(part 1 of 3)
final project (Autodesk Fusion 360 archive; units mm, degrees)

design "final project" references "Enclosure"
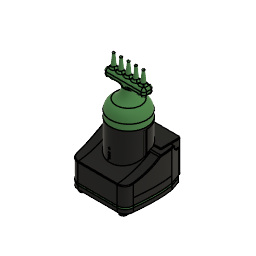
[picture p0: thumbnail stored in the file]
description: Part Number
part number: Micro USB PD Board
part number: Top Toggle Switch
description: STEP AP214
part number: USB Type C Port (SMD Type)
part number: Screw-Terminal-P5.08
part number: ESSOP-10 Package v5
part number: Pin1Body
part number: Pin2Body
part number: CeramicBody
part number: CoatingBody
description: FreeCAD Model
part number: Resistor_0603
part number: Pin1
part number: Pin2
part number: CeramicBody_1
part number: Ceramic_Capacitor_0402_h20mil
part number: 0603 Chip SMD LED (1.6x0.8mm)
sketch "Sketch1" plane through (0, 0, 0) normal (0, 0, 1) x axis (1, 0, 0)
  line L1 (-41, -45) -> (41, -45)
  line L2 (-41, 23.9998) -> (-41, -45)
  line L3 (27.5, 45) -> (-27.5, 45)
  line L4 (41, -45) -> (41, 23.9998)
  line L5 (-41, 45) -> (41, -45)
  line L6 (41, 45) -> (-41, -45)
  line L7 (27.5, 45) -> (0, 45)
  line L8 (-27.5, 45) -> (0, 45)
  line L9 (-27.5, 40) -> (-27.5, 45)
  line L10 (27.5, 40) -> (27.5, 45)
  line L11 (-35.5, 40) -> (-27.5, 40)
  line L12 (-41, 23.9998) -> (-35.5, 40)
  line L13 (35.5, 40) -> (27.5, 40)
  line L14 (41, 23.9998) -> (35.5, 40)
  point P6 (0, 0)
  point P1 (0, 0)
  point P7 (0, 45)
  point P4 (-41, 45)
  point P5 (41, 45)
  point P3 (-41, -45)
  point P8 (27.5, 45)
  point P9 (-27.5, 45)
  point P10 (-27.5, 40)
  point P12 (-35.5, 40)
  point P11 (27.5, 40)
  point P15 (35.5, 40)
  horizontal L1
  perpendicular L1 L2
  parallel L1 L3
  parallel L2 L4
  coincident L5 P6
  coincident L6 P6
  coincident P1 P6
  parallel L3 L7
  parallel L3 L8
  perpendicular L8 L9
  perpendicular L3 L10
  perpendicular L9 L11
  perpendicular L10 L13
  coincident L3 P7
  dimension "d1" distance P4 P5 = 82
  dimension "d2" distance P3 P4 = 90
  dimension "d3" distance P7 P8 = 27.5
  dimension "d4" distance P7 P9 = 27.5
  dimension "d5" distance P10 P12 = 8
  dimension "d6" distance P11 P15 = 8
extrude "Extrude1" new body sketch "Sketch1" profile of L1 L2 L3 L4 L7 L8 L9 L10 L11 L12 L13 L14 along normal blind 7.5
fillet "Fillet2" radius 12
sketch "Sketch2" plane through (0, 0, 7.5) normal (0, 0, 1) x axis (-1, 0, 0)
  line L1 (-41, -23.9998) -> (-41, 33)
  line L2 (-35.5, -40) -> (-41, -23.9998)
  line L3 (-27.5, -40) -> (-35.5, -40)
  line L4 (-27.5, -45) -> (-27.5, -40)
  line L5 (27.5, -45) -> (-27.5, -45)
  line L6 (27.5, -40) -> (27.5, -45)
  line L7 (35.5, -40) -> (27.5, -40)
  line L8 (41, -23.9998) -> (35.5, -40)
  line L9 (41, 33) -> (41, -23.9998)
  line L10 (-29, 45) -> (29, 45)
  curve K1 (41, -23.9998) -> (41, 33)
  line L11 (41, 33.316) -> (41, -23.9998)
  arc A1 centre (-29, 33) radius 12 clockwise from (-41, 33) to (-29, 45)
  arc A2 centre (29, 33) radius 12 clockwise from (29, 45) to (41, 33)
  point P21 (41, 33)
  point P24 (41, 33)
  point P19 (41, -23.9998)
  point P26 (41, -23.9998)
  coincident P21 P24
  coincident P19 P26
  parallel L9 L11
extrude "Extrude2" add sketch "Sketch2" profile of L9 K1 against normal blind 7.5
sketch "Sketch3" plane through (0, 0, 7.5) normal (0, 0, 1) x axis (-1, 0, 0)
  line L1 (-41, -23.9998) -> (-41, 33)
  line L2 (-35.5, -40) -> (-41, -23.9998)
  line L3 (-27.5, -40) -> (-35.5, -40)
  line L4 (-27.5, -45) -> (-27.5, -40)
  line L5 (27.5, -45) -> (-27.5, -45)
  line L6 (27.5, -40) -> (27.5, -45)
  line L7 (35.5, -40) -> (27.5, -40)
  line L8 (41, -23.9998) -> (35.5, -40)
  curve K1 (41, -23.9998) -> (41, 33)
  line L9 (-29, 45) -> (29, 45)
  curve K2 (-41, -23.9998) -> (-41, 33)
  line L10 (-41, 33) -> (-41, -23.9998)
  arc A1 centre (-29, 33) radius 12 clockwise from (-41, 33) to (-29, 45)
  arc A2 centre (29, 33) radius 12 clockwise from (29, 45) to (41, 33)
  tangent A1 L10
extrude "Extrude3" add sketch "Sketch3" profile of L1 K2 against normal blind 7.5
sketch "Sketch4" plane through (0, 0, 7.5) normal (0, 0, 1) x axis (-1, 0, 0)
  curve K1 (-41, -23.9998) -> (-41, 33)
  line L1 (-35.5, -40) -> (-41, -23.9998)
  line L2 (-27.5, -40) -> (-35.5, -40)
  line L3 (-27.5, -45) -> (-27.5, -40)
  line L4 (27.5, -45) -> (-27.5, -45)
  line L5 (27.5, -40) -> (27.5, -45)
  line L6 (35.5, -40) -> (27.5, -40)
  line L7 (41, -23.9998) -> (35.5, -40)
  curve K2 (41, -23.9998) -> (41, 33)
  line L8 (-29, 45) -> (29, 45)
  line L9 (31.5, -51.6365) -> (35.5, -40)
  line L10 (37, -45) -> (27.5, -45)
  line L11 (-27.5, -45) -> (37, -45)
  line L12 (-36, -45) -> (-27.5, -45)
  line L13 (-31, -51) -> (-35.5, -40)
  arc A1 centre (-29, 33) radius 12 clockwise from (-41, 33) to (-29, 45)
  arc A2 centre (29, 33) radius 12 clockwise from (29, 45) to (41, 33)
  point P11 (35.5, -40)
  point P16 (35.5, -40)
  point P9 (27.5, -45)
  point P18 (27.5, -45)
  point P8 (-27.5, -45)
  point P20 (-27.5, -45)
  point P21 (-27.5, -45)
  point P6 (-35.5, -40)
  point P23 (-35.5, -40)
  coincident P11 P16
  parallel L7 L9
  coincident P9 P18
  perpendicular L5 L10
  coincident P8 P20
  coincident P8 P21
  perpendicular L3 L12
  coincident P6 P23
fillet "Fillet3" radius 2
extrude "Extrude4" new body sketch "Sketch4" along normal blind 35
fillet "Fillet5" radius 4
sketch "Sketch5" plane through (0, 0, 0) normal (1, 0, 0) x axis (0, 1, 0)
  line L1 (-40, 25) -> (-40, 0)
  line L2 (5, 25) -> (-40, 25)
  line L3 (5, 42.7761) -> (5, 25)
  line L4 (-46.8828, 42.7761) -> (5, 42.7761)
  line L5 (-48.9914, 25) -> (-46.8828, 42.7761)
  line L6 (-40, 25) -> (-48.9914, 25)
  point P2 (-40, 0)
  point P3 (-40, 25)
  vertical L1
  perpendicular L1 L2
  perpendicular L2 L3
  perpendicular L3 L4
  perpendicular L1 L6
  dimension "d26" distance P2 P3 = 25
extrude "Extrude5" cut sketch "Sketch5" profile of L2 L3 L4 L5 L6 distance 65
chamfer "Chamfer1" distance 17.5
sketch "Sketch6" plane through (0, 0, 42.5) normal (0, 0, 1) x axis (-1, 0, 0)
  line L1 (-42.7553, -5) -> (42.7553, -5)
  curve K1 (-41, -23.9998) -> (-42.7553, -5)
  line L2 (-35.5, -40) -> (-41, -23.9998)
  line L3 (-34.4713, -42.5145) -> (-35.5, -40)
  line L4 (30.9265, -45) -> (-30.7691, -45)
  line L5 (41, -23.9998) -> (34.7093, -42.3003)
  curve K2 (42.7553, -5) -> (41, -23.9998)
  arc A1 centre (-30.7691, -41) radius 4 clockwise from (-30.7691, -45) to (-34.4713, -42.5145)
  arc A2 centre (30.9265, -41) radius 4 clockwise from (34.7093, -42.3003) to (30.9265, -45)
fillet "Fillet6" radius 5
fillet "Fillet7" radius 115
sketch "Sketch7" plane through (0, 0, 7.5) normal (0, 0, -1) x axis (1, 0, 0)
  line L1 (30.7691, -45) -> (-30.9265, -45)
  line L2 (35.5, -40) -> (34.4713, -42.5145)
  line L3 (41, -23.9998) -> (35.5, -40)
  curve K1 (41, -23.9998) -> (41, 33)
  line L4 (-29, 45) -> (29, 45)
  curve K2 (-41, -23.9998) -> (-41, 33)
  line L5 (-34.7093, -42.3003) -> (-41, -23.9998)
  line L6 (-15, -30) -> (15, -30)
  line L7 (-15, -20) -> (15, -30)
  line L8 (15, -20) -> (-15, -30)
  line L9 (0, -15) -> (0, -25)
  line L10 (-20, -15) -> (-15, -30)
  line L11 (20, -15) -> (15, -30)
  arc A1 centre (-30.9265, -41) radius 4 clockwise from (-30.9265, -45) to (-34.7093, -42.3003)
  arc A2 centre (30.7691, -41) radius 4 clockwise from (34.4713, -42.5145) to (30.7691, -45)
  arc A3 centre (29, 33) radius 12 clockwise from (29, 45) to (41, 33)
  arc A4 centre (-29, 33) radius 12 clockwise from (-41, 33) to (-29, 45)
  circle C1 centre (0, 0) radius 25
  point P1 (0, 0)
  point P17 (0, 0)
  point P22 (0, -25)
  point P23 (0, -25)
  point P25 (-20, -15)
  point P26 (20, -15)
  point P20 (-15, -20)
  point P21 (15, -20)
  point P19 (-15, -30)
  coincident P1 P17
  horizontal L6
  coincident L7 P22
  coincident L8 P22
  coincident C1 P22
  coincident P22 P23
  vertical L9
  coincident C1 P25
  perpendicular L8 L10
  coincident C1 P26
  perpendicular L7 L11
  dimension "d34" diameter C1 = 50
  dimension "d35" distance P20 P21 = 30
  dimension "d36" distance P19 P20 = 10
sketch "Sketch9" plane through (0, 0, 0) normal (0, 0, -1) x axis (1, 0, 0)
  line L1 (25.5, -45) -> (-25.5, -45)
  line L2 (27.5, -42) -> (27.5, -43)
  line L3 (34.0726, -40) -> (29.5, -40)
  line L4 (41, -23.9998) -> (35.964, -38.6502)
  curve K1 (41, 33) -> (41, -23.9998)
  line L5 (-29, 45) -> (29, 45)
  curve K2 (-41, -23.9998) -> (-41, 33)
  line L6 (-35.964, -38.6502) -> (-41, -23.9998)
  line L7 (-29.5, -40) -> (-34.0726, -40)
  line L8 (-27.5, -43) -> (-27.5, -42)
  line L9 (-26.4645, -26.4645) -> (-30, -30)
  line L10 (26.4645, -26.4645) -> (30, -30)
  arc A1 centre (-25.5, -43) radius 2 clockwise from (-25.5, -45) to (-27.5, -43)
  arc A2 centre (25.5, -43) radius 2 clockwise from (27.5, -43) to (25.5, -45)
  arc A3 centre (29.5, -42) radius 2 clockwise from (27.5, -42) to (29.5, -40)
  arc A4 centre (34.0726, -38) radius 2 clockwise from (35.964, -38.6502) to (34.0726, -40)
  arc A5 centre (29, 33) radius 12 clockwise from (29, 45) to (41, 33)
  arc A6 centre (-29, 33) radius 12 clockwise from (-41, 33) to (-29, 45)
  arc A7 centre (-34.0726, -38) radius 2 clockwise from (-34.0726, -40) to (-35.964, -38.6502)
  arc A8 centre (-29.5, -42) radius 2 clockwise from (-29.5, -40) to (-27.5, -42)
  circle C1 centre (30, -30) radius 5
  circle C2 centre (30, -30) radius 4
  circle C3 centre (-30, -30) radius 5
  circle C4 centre (-30, -30) radius 4
  circle C5 centre (30, 36.9675) radius 5
  circle C6 centre (30, 36.9675) radius 4
  circle C7 centre (-30, 36.9675) radius 5
  circle C8 centre (-30, 36.9675) radius 4
  point P30 (0, 0)
  point P1 (0, 0)
  point P29 (30, -30)
  point P31 (30, -30)
  point P28 (-30, -30)
  point P33 (-30, -30)
  point P35 (-26.4645, -26.4645)
  point P36 (26.4645, -26.4645)
  coincident L9 P30
  coincident P1 P30
  coincident P29 P31
  concentric C1 C2
  coincident P28 P33
  concentric C3 C4
  coincident C3 P35
  coincident C1 P36
  concentric C5 C6
  concentric C7 C8
  dimension "d47" diameter C1 = 10
  dimension "d48" diameter C2 = 8
  dimension "d49" diameter C3 = 10
  dimension "d50" diameter C4 = 8
  dimension "d51" diameter C5 = 10
  dimension "d52" diameter C6 = 8
  dimension "d53" diameter C7 = 10
  dimension "d54" diameter C8 = 8
extrude "Extrude8" add sketch "Sketch9" profile of C1 C2 C3 C4 C5 C6 C7 C8 along normal blind 2
chamfer "Chamfer3" distance 2
sketch "Sketch13" plane through (0, 0, 42.5) normal (0, 0, 1) x axis (-1, 0, 0)
  line L1 (-42.6731, -7.0711) -> (42.6731, -7.0711)
  line L2 (19, -36.2164) -> (-19, -36.2164)
  line L3 (19, -23.2164) -> (19, -36.2164)
  line L4 (-19, -36.2164) -> (-19, -23.2164)
  curve K1 (-41, -23.9998) -> (-42.6731, -7.0711)
  line L5 (-35.5, -40) -> (-41, -23.9998)
  line L6 (-34.4713, -42.5145) -> (-35.5, -40)
  line L7 (30.9265, -45) -> (-30.7691, -45)
  line L8 (41, -23.9998) -> (34.7093, -42.3003)
  curve K2 (42.6731, -7.0711) -> (41, -23.9998)
  arc A1 centre (0, 0) radius 30 clockwise from (19, -23.2164) to (-19, -23.2164)
  arc A2 centre (-30.7691, -41) radius 4 clockwise from (-30.7691, -45) to (-34.4713, -42.5145)
  arc A3 centre (30.9265, -41) radius 4 clockwise from (34.7093, -42.3003) to (30.9265, -45)
  point P1 (0, 0)
  point P4 (0, 0)
  point P7 (19, -23.2164)
  coincident P1 P4
  horizontal L2
  perpendicular L2 L3
  parallel L3 L4
  dimension "d77" distance L2 P7 = 13
chamfer "Chamfer6" distance 0.5
sketch "Sketch14" plane through (0, 0, 42.5) normal (0, 0, 1) x axis (-1, 0, 0)
  line L1 (-42.6731, -7.0711) -> (42.6731, -7.0711)
  line L2 (-45, -19.0561) -> (34.7114, -19.0561)
  line L3 (-60, -29.7451) -> (56.5385, -29.7451)
  line L4 (55.1805, -42.4902) -> (34.7114, -42.2654)
  line L5 (55.1805, -29.7451) -> (55.1805, -42.4902)
  line L6 (38.8772, -43.1883) -> (39.0249, -29.7451)
  line L7 (34.7114, -45.6177) -> (34.7954, -29.7451)
  curve K1 (-41, -23.9998) -> (-42.6731, -7.0711)
  line L8 (-35.5, -40) -> (-41, -23.9998)
  line L9 (-34.4713, -42.5145) -> (-35.5, -40)
  line L10 (30.9265, -45) -> (-30.7691, -45)
  line L11 (41, -23.9998) -> (34.7093, -42.3003)
  curve K2 (42.6731, -7.0711) -> (41, -23.9998)
  line L12 (0.0787, -53.7604) -> (0, 0)
  line L13 (-38.7506, -43.3019) -> (-38.9376, -29.8592)
  line L14 (-55.0559, -42.6516) -> (-34.5875, -42.3668)
  line L15 (-34.5777, -45.7191) -> (-34.7081, -29.8468)
  line L16 (60.0868, -29.5693) -> (-56.4512, -29.9105)
  arc A1 centre (-30.7691, -41) radius 4 clockwise from (-30.7691, -45) to (-34.4713, -42.5145)
  arc A2 centre (30.9265, -41) radius 4 clockwise from (34.7093, -42.3003) to (30.9265, -45)
  point P11 (55.1805, -29.7451)
  point P12 (39.0249, -29.7451)
  point P14 (34.7954, -29.7451)
  point P1 (0, 0)
  point P25 (0, 0)
  point P5 (34.7114, -42.2654)
  point P29 (-34.5875, -42.3668)
  point P8 (56.5385, -29.7451)
  point P33 (-56.4512, -29.9105)
  point P9 (-60, -29.7451)
  point P34 (60.0868, -29.5693)
  point P10 (55.1805, -42.4902)
  point P30 (-55.0559, -42.6516)
  point P27 (-38.9376, -29.8592)
  point P13 (38.8772, -43.1883)
  point P28 (-38.7506, -43.3019)
  point P31 (-34.7081, -29.8468)
  point P15 (34.7114, -45.6177)
  point P32 (-34.5777, -45.7191)
  coincident L3 P11
  perpendicular L3 L5
  coincident L3 P12
  perpendicular L4 L6
  coincident L3 P14
  coincident P1 P25
  symmetric P5 L12 P29
  symmetric P8 L12 P33
  symmetric P9 L12 P34
  symmetric P10 L12 P30
  symmetric P12 L12 P27
  symmetric P13 L12 P28
  symmetric P14 L12 P31
  symmetric P15 L12 P32
extrude "Extrude10" cut sketch "Sketch14" profile of L3 L4 L6 L7 L8 L9 L11 L13 L14 L15 L16 against normal blind 10
chamfer "Chamfer7" distance 5
sketch "Sketch15" plane through (0, 0, 42.5) normal (0, 0, 1) x axis (-1, 0, 0)
  line L1 (34.7954, -29.7451) -> (34.7292, -42.2422)
  line L2 (39.0249, -29.7451) -> (34.7954, -29.7451)
  line L3 (39.0249, -29.7457) -> (39.0249, -29.7451)
  line L4 (41, -23.9998) -> (39.0249, -29.7457)
  curve K1 (42.6731, -7.0711) -> (41, -23.9998)
  line L5 (-42.6731, -7.0711) -> (42.6731, -7.0711)
  curve K2 (-41, -23.9998) -> (-42.6731, -7.0711)
  line L6 (-38.9356, -30.0054) -> (-41, -23.9998)
  line L7 (-38.9376, -29.8592) -> (-38.9356, -30.0054)
  line L8 (-34.7081, -29.8468) -> (-38.9376, -29.8592)
  line L9 (-34.6067, -42.1835) -> (-34.7081, -29.8468)
  line L10 (-34.4713, -42.5145) -> (-34.6067, -42.1835)
  line L11 (30.9265, -45) -> (-30.7691, -45)
  line L12 (34.7292, -42.2422) -> (34.7093, -42.3003)
  line L13 (34.8734, -14.9854) -> (34.7954, -29.7451)
  line L14 (-34.8303, -14.9854) -> (-34.7081, -29.8468)
  line L15 (34.8734, -14.9854) -> (-34.8303, -14.9854)
  arc A1 centre (-30.7691, -41) radius 4 clockwise from (-30.7691, -45) to (-34.4713, -42.5145)
  arc A2 centre (30.9265, -41) radius 4 clockwise from (34.7093, -42.3003) to (30.9265, -45)
  point P3 (34.7954, -29.7451)
  point P21 (34.7954, -29.7451)
  point P13 (-34.7081, -29.8468)
  point P23 (-34.7081, -29.8468)
  coincident P3 P21
  coincident P13 P23
  horizontal L15
extrude "Extrude11" add sketch "Sketch15" profile of L1 L9 L10 A1 L11 A2 L12 L13 L14 L15 along normal blind 1
fillet "Fillet16" radius 1
chamfer "Chamfer11" distance 1
fillet "Fillet23" radius 4
fillet "Fillet24" radius 4
chamfer "Chamfer12" distance 1
move "Move1"
sketch "Sketch17" plane through (0, 0, 7.5) normal (0, 0, 1) x axis (-1, 0, 0)
  line L1 (-87.5, -42) -> (-87.5, -43)
  line L2 (-80.9274, -40) -> (-85.5, -40)
  line L3 (-74, -23.9998) -> (-79.036, -38.6502)
  curve K1 (-74, -23.9998) -> (-74, 33)
  line L4 (-144, 45) -> (-86, 45)
  curve K2 (-156, -23.9998) -> (-156, 33)
  line L5 (-150.964, -38.6502) -> (-156, -23.9998)
  line L6 (-144.5, -40) -> (-149.0726, -40)
  line L7 (-142.5, -43) -> (-142.5, -42)
  line L8 (-89.5, -45) -> (-140.5, -45)
  arc A1 centre (-89.5, -43) radius 2 clockwise from (-87.5, -43) to (-89.5, -45)
  arc A2 centre (-85.5, -42) radius 2 clockwise from (-87.5, -42) to (-85.5, -40)
  arc A3 centre (-80.9274, -38) radius 2 clockwise from (-79.036, -38.6502) to (-80.9274, -40)
  arc A4 centre (-86, 33) radius 12 clockwise from (-86, 45) to (-74, 33)
  arc A5 centre (-144, 33) radius 12 clockwise from (-156, 33) to (-144, 45)
  arc A6 centre (-149.0726, -38) radius 2 clockwise from (-149.0726, -40) to (-150.964, -38.6502)
  arc A7 centre (-144.5, -42) radius 2 clockwise from (-144.5, -40) to (-142.5, -42)
  arc A8 centre (-140.5, -43) radius 2 clockwise from (-140.5, -45) to (-142.5, -43)
extrude "Extrude1" new body sketch "Sketch17" along normal blind 3
move "Move1"
shell "Shell1" innerThickness 3
sketch "Sketch18" plane through (0, 0, 3) normal (0, 0, 1) x axis (-1, 0, 0)
  line L1 (-90.737, -41.7574) -> (-139.263, -41.7574)
  line L2 (-81.8142, -36.7574) -> (-85.5, -36.7574)
  line L3 (-77.1602, -23.2182) -> (-81.8142, -36.7574)
  curve K1 (-77.1602, -23.2182) -> (-77.244, 32.8474)
  line L4 (-144, 41.7574) -> (-86, 41.7574)
  curve K2 (-152.756, 32.8474) -> (-152.8398, -23.2182)
  line L5 (-148.1858, -36.7574) -> (-152.8398, -23.2182)
  line L6 (-144.5, -36.7574) -> (-148.1858, -36.7574)
  arc A1 centre (-85.5, -42) radius 5.2426 clockwise from (-90.737, -41.7574) to (-85.5, -36.7574)
  arc A2 centre (-86, 33) radius 8.7574 clockwise from (-86, 41.7574) to (-77.244, 32.8474)
  arc A3 centre (-144, 33) radius 8.7574 clockwise from (-152.756, 32.8474) to (-144, 41.7574)
  arc A4 centre (-144.5, -42) radius 5.2426 clockwise from (-144.5, -36.7574) to (-139.263, -41.7574)
  circle C1 centre (-90, -30) radius 5
  circle C2 centre (-140, -30) radius 5
  circle C3 centre (-140, 30) radius 5
  circle C4 centre (-90, 30) radius 5
  dimension "d116" diameter C1 = 10
  dimension "d117" diameter C2 = 10
  dimension "d118" diameter C3 = 10
  dimension "d119" diameter C4 = 10
sketch "Sketch19" plane through (0, 0, 7.507) normal (0, 0, 1) x axis (-1, 0, 0)
  circle C1 centre (-90, -30) radius 5
  circle C2 centre (-90, -30) radius 2.5
  circle C3 centre (-140, -30) radius 2.5
  circle C4 centre (-140, 30) radius 2.5
  circle C5 centre (-90, 30) radius 2.5
  concentric C1 C2
  dimension "d122" diameter C2 = 5
  dimension "d123" diameter C3 = 5
  dimension "d124" diameter C4 = 5
  dimension "d125" diameter C5 = 5
align "Align1"
align "Align2"
move "Move2"
move "Move3"
move "Move4"
sketch "Sketch20" plane through (0, 0, 10.7) normal (0, 0, 1) x axis (-1, 0, 0)
  line L1 (-142.5, -43) -> (-142.5, -42)
  line L2 (-89.5, -45) -> (-140.5, -45)
  line L3 (-87.5, -42) -> (-87.5, -43)
  line L4 (-80.9274, -40) -> (-85.5, -40)
  line L5 (-74, -23.9998) -> (-79.036, -38.6502)
  curve K1 (-74, 33) -> (-74, -23.9998)
  line L6 (-144, 45) -> (-86, 45)
  curve K2 (-156, -23.9998) -> (-156, 33)
  line L7 (-150.964, -38.6502) -> (-156, -23.9998)
  line L8 (-144.5, -40) -> (-149.0726, -40)
  line L9 (-85, -15) -> (-90, -15)
  line L10 (-85, 15) -> (-85, -15)
  line L11 (-145, 15) -> (-140, 15)
  line L12 (-145, -15) -> (-145, 15)
  line L13 (-85, 15) -> (-145, -15)
  line L14 (-145, 15) -> (-85, -15)
  line L15 (-100, -35) -> (-130, -35)
  line L16 (-100, -25) -> (-100, -35)
  line L17 (-130, 35) -> (-100, 35)
  line L18 (-130, 25) -> (-130, 35)
  line L19 (-100, 35) -> (-130, -35)
  line L20 (-130, 35) -> (-100, -35)
  line L21 (-130, -25) -> (-130, -35)
  line L22 (-140, -15) -> (-145, -15)
  line L23 (-90, 15) -> (-85, 15)
  line L24 (-100, 25) -> (-100, 35)
  arc A1 centre (-140.5, -43) radius 2 clockwise from (-140.5, -45) to (-142.5, -43)
  arc A2 centre (-89.5, -43) radius 2 clockwise from (-87.5, -43) to (-89.5, -45)
  arc A3 centre (-85.5, -42) radius 2 clockwise from (-87.5, -42) to (-85.5, -40)
  arc A4 centre (-80.9274, -38) radius 2 clockwise from (-79.036, -38.6502) to (-80.9274, -40)
  arc A5 centre (-86, 33) radius 12 clockwise from (-86, 45) to (-74, 33)
  arc A6 centre (-144, 33) radius 12 clockwise from (-156, 33) to (-144, 45)
  arc A7 centre (-149.0726, -38) radius 2 clockwise from (-149.0726, -40) to (-150.964, -38.6502)
  arc A8 centre (-144.5, -42) radius 2 clockwise from (-144.5, -40) to (-142.5, -42)
  arc A9 centre (-90, -25) radius 10 clockwise from (-100, -25) to (-90, -15)
  arc A10 centre (-140, 25) radius 10 clockwise from (-130, 25) to (-140, 15)
  arc A11 centre (-90, 25) radius 10 clockwise from (-90, 15) to (-100, 25)
  arc A12 centre (-140, -25) radius 10 clockwise from (-140, -15) to (-130, -25)
  point P32 (-115, 0)
  point P37 (-115, 0)
  point P28 (-145, -15)
  point P35 (-100, 35)
  point P30 (-85, 15)
  point P33 (-130, -35)
  horizontal L9
  perpendicular L9 L10
  parallel L9 L11
  parallel L10 L12
  coincident L13 P32
  coincident L14 P32
  horizontal L15
  perpendicular L15 L16
  parallel L15 L17
  parallel L16 L18
  coincident L19 P37
  coincident L20 P37
  coincident P32 P37
  coincident P28 L9
  coincident P35 L16
  tangent L9 A9
  tangent L16 A9
  coincident P30 L11
  coincident P33 L18
  tangent L11 A10
  tangent L18 A10
  equal A9 A10
  perpendicular L15 L21
  perpendicular L21 L22
  perpendicular L10 L23
  perpendicular L23 L24
  tangent L23 A11
  tangent L24 A11
  tangent L21 A12
  tangent L22 A12
  equal A11 A12
  dimension "d128" radius A9 = 10
  dimension "d129" radius A11 = 10
extrude "Extrude2" cut sketch "Sketch20" profile of L9 L10 L11 L12 L15 L16 L17 L18 A9 A10 L21 L22 L23 L24 A11 A12 against normal blind 3
move "Move2"
move "Move3"
move "Move4"
align "Align3"
align "Align4"
align "Align1"
move "Move5"
move "Move6"
move "Move7"
move "Move8"
move "Move9"
move "Move9"
move "Move10"
move "Move11"
move "Move12"
move "Move13"
sketch "Sketch21" plane through (0, 0, -45.1905) normal (0, 0, -1) x axis (1, 0, 0)
  line L1 (-319.8008, -68.5715) -> (-381.4964, -68.5715)
  line L2 (-315.0699, -63.5715) -> (-316.0986, -66.086)
  line L3 (-309.5699, -47.5713) -> (-315.0699, -63.5715)
  curve K1 (-391.5699, -47.5713) -> (-391.5699, 9.4285)
  line L4 (-385.2792, -65.8718) -> (-391.5699, -47.5713)
  line L5 (-330, 15) -> (-370, 15)
  line L6 (-330, -2.5971) -> (-330, 15)
  line L7 (-315, -2.5971) -> (-330, -2.5971)
  line L8 (-315, -45) -> (-315, -2.5971)
  line L9 (-332.7496, -45) -> (-315, -45)
  line L10 (-332.7496, -60) -> (-332.7496, -45)
  line L11 (-367.1133, -60) -> (-332.7496, -60)
  line L12 (-367.1133, -45) -> (-367.1133, -60)
  line L13 (-385, -45) -> (-367.1133, -45)
  line L14 (-385, 0) -> (-385, -45)
  line L15 (-370, 0) -> (-385, 0)
  line L16 (-370, 15) -> (-370, 0)
  curve K2 (-309.5699, -47.5713) -> (-309.5699, 9.4285)
  line L17 (-379.5699, 21.4285) -> (-321.5699, 21.4285)
  arc A1 centre (-381.4964, -64.5715) radius 4 clockwise from (-381.4964, -68.5715) to (-385.2792, -65.8718)
  arc A2 centre (-319.8008, -64.5715) radius 4 clockwise from (-316.0986, -66.086) to (-319.8008, -68.5715)
  arc A3 centre (-379.5699, 9.4285) radius 12 clockwise from (-391.5699, 9.4285) to (-379.5699, 21.4285)
  arc A4 centre (-321.5699, 9.4285) radius 12 clockwise from (-321.5699, 21.4285) to (-309.5699, 9.4285)
  horizontal L5
  perpendicular L5 L6
  perpendicular L6 L7
  perpendicular L7 L8
  perpendicular L8 L9
  perpendicular L9 L10
  perpendicular L8 L11
  perpendicular L11 L12
  perpendicular L12 L13
  perpendicular L13 L14
  perpendicular L14 L15
  perpendicular L5 L16
extrude "Extrude14" cut sketch "Sketch21" profile of L5 L6 L7 L8 L9 L10 L11 L12 L13 L14 L15 L16 against normal blind 6
move "Move14"
component_insert "Component Insert"
extrude "Extrude16" add of existing geometry blind 6
work_plane "WorkPlane3" AlongDistance -30
sketch "Sketch22" plane through (0, 0, -3) normal (0, 0, -1) x axis (-1, 0, 0)
  curve K1 (160.1791, -26.2406) -> (162.8724, -26.088)
  arc A1 centre (160, 0.7588) radius 27 clockwise from (162.9191, -26.0829) to (160.464, -26.2372)
  arc A2 centre (160, 0.7588) radius 27 clockwise from (162.9191, -26.0829) to (160.464, -26.2372)
  arc A3 centre (160, 0.7588) radius 27 clockwise from (162.9191, -26.0829) to (160.464, -26.2372)
  arc A4 centre (160, 0.7588) radius 27 clockwise from (162.9191, -26.0829) to (160.464, -26.2372)
  arc A5 centre (160, 0.7588) radius 27 clockwise from (162.9191, -26.0829) to (160.464, -26.2372)
  arc A6 centre (160, 0.7588) radius 27 clockwise from (162.9191, -26.0829) to (160.464, -26.2372)
  arc A7 centre (160, 0.7588) radius 27 clockwise from (133.0017, 0.4588) to (187, 0.7588)
  arc A8 centre (160, 0.7588) radius 27 clockwise from (187, 0.7588) to (133.0017, 0.4588)
  circle C1 centre (160, 0.7588) radius 27
extrude "Extrude15" cut sketch "Sketch22" profile of A1 A2 A3 A4 A5 A6 A7 A8 C1 along normal blind 13.5 and against normal blind 25
work_plane "WorkPlane4"
extrude "Extrude17" add of existing geometry blind 0.845
fillet "Fillet29" radius 6
move "Move15"
move "Move10"
sketch "Sketch23" plane through (0, 0, 59.345) normal (0, 0, 1) x axis (-1, 0, 0)
  line L1 (170.15, -2.9088) -> (149.85, -2.9088)
  line L2 (170.15, 1.3912) -> (170.15, -2.9088)
  line L3 (149.85, 1.3912) -> (170.15, 1.3912)
  line L4 (149.85, -2.9088) -> (149.85, 1.3912)
  line L5 (170.15, 1.3912) -> (149.85, -2.9088)
  line L6 (149.85, 1.3912) -> (170.15, -2.9088)
  circle C1 centre (160, -0.7588) radius 21
  point P7 (160, -0.7588)
  point P2 (160, -0.7588)
  point P5 (170.15, 1.3912)
  point P6 (149.85, 1.3912)
  point P4 (170.15, -2.9088)
  horizontal L1
  perpendicular L1 L2
  parallel L1 L3
  parallel L2 L4
  coincident L5 P7
  coincident L6 P7
  coincident P2 P7
  dimension "d153" distance P5 P6 = 20.3
  dimension "d154" distance P4 P5 = 4.3
extrude "Extrude18" cut sketch "Sketch23" profile of L1 L2 L3 L4 against normal blind 10
fillet "Fillet30" radius 2
sketch "Sketch24" plane through (0, 0, 52.6235) normal (0, 0, -1) x axis (1, 0, 0)
  line L1 (-168.15, -2.9088) -> (-151.85, -2.9088)
  line L2 (-170.15, -0.6088) -> (-170.15, -0.9088)
  line L3 (-151.85, 1.3912) -> (-168.15, 1.3912)
  line L4 (-149.85, -0.9088) -> (-149.85, -0.6088)
  line L5 (-129.0798, -44.5715) -> (-190.7755, -44.5715)
  line L6 (-124.349, -39.5715) -> (-125.3776, -42.086)
  line L7 (-118.849, -23.5713) -> (-124.349, -39.5715)
  curve K1 (-118.849, -23.5713) -> (-118.849, 33.4285)
  line L8 (-188.849, 45.4285) -> (-130.849, 45.4285)
  curve K2 (-200.849, -23.5713) -> (-200.849, 33.4285)
  line L9 (-194.5583, -41.8718) -> (-200.849, -23.5713)
  curve K3 (-196.9505, -22.6076) -> (-196.8469, 33.2448)
  line L10 (-190.7755, -40.5715) -> (-196.9505, -22.6076)
  line L11 (-129.0798, -40.5715) -> (-190.7755, -40.5715)
  line L12 (-128.0945, -38.1629) -> (-129.0798, -40.5715)
  line L13 (-122.7474, -22.6076) -> (-128.0945, -38.1629)
  curve K4 (-122.7474, -22.6076) -> (-122.8511, 33.2448)
  line L14 (-188.849, 41.4285) -> (-130.849, 41.4285)
  arc A1 centre (-168.15, -0.9088) radius 2 clockwise from (-168.15, -2.9088) to (-170.15, -0.9088)
  arc A2 centre (-168.15, -0.6088) radius 2 clockwise from (-170.15, -0.6088) to (-168.15, 1.3912)
  arc A3 centre (-151.85, -0.6088) radius 2 clockwise from (-151.85, 1.3912) to (-149.85, -0.6088)
  arc A4 centre (-151.85, -0.9088) radius 2 clockwise from (-149.85, -0.9088) to (-151.85, -2.9088)
  arc A5 centre (-190.7755, -40.5715) radius 4 clockwise from (-190.7755, -44.5715) to (-194.5583, -41.8718)
  arc A6 centre (-129.0798, -40.5715) radius 4 clockwise from (-125.3776, -42.086) to (-129.0798, -44.5715)
  arc A7 centre (-130.849, 33.4285) radius 12 clockwise from (-130.849, 45.4285) to (-118.849, 33.4285)
  arc A8 centre (-188.849, 33.4285) radius 12 clockwise from (-200.849, 33.4285) to (-188.849, 45.4285)
  arc A9 centre (-130.849, 33.4285) radius 8 clockwise from (-130.849, 41.4285) to (-122.8511, 33.2448)
  arc A10 centre (-188.849, 33.4285) radius 8 clockwise from (-196.8469, 33.2448) to (-188.849, 41.4285)
  dimension "d159" = -4
extrude "Extrude19" cut sketch "Sketch24" profile of L1 A1 L2 A2 L3 A3 L4 A4 L14 K3 K4 L11 L10 L12 L13 A9 A10 against normal blind 4.3
base_feature "Base Feature1"
base_feature "Base Feature1"
base_feature "Base Feature1"
base_feature "Base Feature1"
base_feature "Base Feature1"
base_feature "Base Feature1"
base_feature "Base Feature1"
base_feature "Base Feature1"
base_feature "Base Feature1"
base_feature "Base Feature1"
base_feature "Base Feature1"
base_feature "Base Feature1"
base_feature "Base Feature1"
base_feature "Base Feature1"
base_feature "Base Feature1"
base_feature "Base Feature1"
base_feature "Base Feature1"
base_feature "Base Feature1"
base_feature "Base Feature1"
base_feature "Base Feature1"
base_feature "Base Feature1"
base_feature "Base Feature1"
as_built_joint "As-built2"
position "Position1"
position "Position2"
sketch "Sketch27" plane through (0, 0, 56.9235) normal (0, 0, -1) x axis (1, 0, 0)
  line L1 (-170.15, -0.6088) -> (-170.15, -0.9088)
  line L2 (-151.85, 1.3912) -> (-168.15, 1.3912)
  line L3 (-149.85, -0.9088) -> (-149.85, -0.6088)
  line L4 (-168.15, -2.9088) -> (-151.85, -2.9088)
  line L5 (-188.849, 41.4285) -> (-130.849, 41.4285)
  curve K1 (-196.8469, 33.2448) -> (-196.9505, -22.6076)
  line L6 (-190.7755, -40.5715) -> (-196.9505, -22.6076)
  line L7 (-129.0798, -40.5715) -> (-190.7755, -40.5715)
  line L8 (-128.0945, -38.1629) -> (-129.0798, -40.5715)
  line L9 (-122.7474, -22.6076) -> (-128.0945, -38.1629)
  curve K2 (-122.7474, -22.6076) -> (-122.8511, 33.2448)
  arc A1 centre (-168.15, -0.9088) radius 2 clockwise from (-168.15, -2.9088) to (-170.15, -0.9088)
  arc A2 centre (-168.15, -0.6088) radius 2 clockwise from (-170.15, -0.6088) to (-168.15, 1.3912)
  arc A3 centre (-151.85, -0.6088) radius 2 clockwise from (-151.85, 1.3912) to (-149.85, -0.6088)
  arc A4 centre (-151.85, -0.9088) radius 2 clockwise from (-149.85, -0.9088) to (-151.85, -2.9088)
  arc A5 centre (-130.849, 33.4285) radius 8 clockwise from (-130.849, 41.4285) to (-122.8511, 33.2448)
  arc A6 centre (-188.849, 33.4285) radius 8 clockwise from (-196.8469, 33.2448) to (-188.849, 41.4285)
  circle C1 centre (-160, -0.9088) radius 20
  dimension "d162" diameter C1 = 40
extrude "Extrude20" add of existing geometry blind 10
extrude "Extrude21" add sketch "Sketch27" profile of A5 L5 A6 K1 L6 L7 L8 L9 K2 C1 along normal blind 14.3
position "Position3"
sketch "Sketch28" plane through (0, 44.62, 0) normal (0, 1, 0) x axis (-1, 0, 0)
  line L1 (143.38, 52.67) -> (143.38, 51.96)
  line L2 (135.69, 53.92) -> (142.13, 53.92)
  line L3 (134.44, 51.96) -> (134.44, 52.67)
  line L4 (142.13, 50.71) -> (135.69, 50.71)
  line L5 (134.59, 52.67) -> (134.59, 51.96)
  line L6 (142.13, 53.77) -> (135.69, 53.77)
  line L7 (143.23, 51.96) -> (143.23, 52.67)
  line L8 (135.69, 50.86) -> (142.13, 50.86)
  arc A1 centre (142.13, 52.67) radius 1.25 clockwise from (142.13, 53.92) to (143.38, 52.67)
  arc A2 centre (135.69, 52.67) radius 1.25 clockwise from (134.44, 52.67) to (135.69, 53.92)
  arc A3 centre (135.69, 51.96) radius 1.25 clockwise from (135.69, 50.71) to (134.44, 51.96)
  arc A4 centre (142.13, 51.96) radius 1.25 clockwise from (143.38, 51.96) to (142.13, 50.71)
  arc A5 centre (135.69, 51.96) radius 1.1 clockwise from (135.69, 50.86) to (134.59, 51.96)
  arc A6 centre (135.69, 52.67) radius 1.1 clockwise from (134.59, 52.67) to (135.69, 53.77)
  arc A7 centre (142.13, 52.67) radius 1.1 clockwise from (142.13, 53.77) to (143.23, 52.67)
  arc A8 centre (142.13, 51.96) radius 1.1 clockwise from (143.23, 51.96) to (142.13, 50.86)
sketch "Sketch29" plane through (0, 0, 42.6235) normal (0, 0, -1) x axis (1, 0, 0)
  line L1 (-129.0798, -44.5715) -> (-190.7755, -44.5715)
  line L2 (-124.349, -39.5715) -> (-125.3776, -42.086)
  line L3 (-118.849, -23.5713) -> (-124.349, -39.5715)
  curve K1 (-118.849, 33.4285) -> (-118.849, -23.5713)
  line L4 (-188.849, 45.4285) -> (-130.849, 45.4285)
  curve K2 (-200.849, -23.5713) -> (-200.849, 33.4285)
  line L5 (-194.5583, -41.8718) -> (-200.849, -23.5713)
  line L6 (-145, -43) -> (-132, -43)
  line L7 (-145, -17) -> (-145, -43)
  line L8 (-132, -17) -> (-145, -17)
  line L9 (-132, -43) -> (-132, -17)
  circle C1 centre (-160, -0.9088) radius 20
  arc A1 centre (-190.7755, -40.5715) radius 4 clockwise from (-190.7755, -44.5715) to (-194.5583, -41.8718)
  arc A2 centre (-129.0798, -40.5715) radius 4 clockwise from (-125.3776, -42.086) to (-129.0798, -44.5715)
  arc A3 centre (-130.849, 33.4285) radius 12 clockwise from (-130.849, 45.4285) to (-118.849, 33.4285)
  arc A4 centre (-188.849, 33.4285) radius 12 clockwise from (-200.849, 33.4285) to (-188.849, 45.4285)
  point P18 (-132, -43)
  point P21 (-132, -17)
  point P20 (-145, -17)
  horizontal L6
  vertical L7
  horizontal L8
  vertical L9
  dimension "d169" distance P18 P21 = 26
  dimension "d170" distance P20 P21 = 13
extrude "Extrude22" cut sketch "Sketch29" profile of L6 L7 L8 L9 against normal blind 15
extrude "Extrude23" cut sketch "Sketch28" profile of A5 L5 A6 L6 A7 L7 A8 L8 against normal blind 11
offset_faces "OffsetFaces1" distance -0.4
sketch "Sketch30" plane through (0, 0, 42.6235) normal (0, 0, -1) x axis (1, 0, 0)
  line L1 (-145, -17) -> (-145, -43)
  line L2 (-132, -17) -> (-145, -17)
  line L3 (-132, -43) -> (-132, -17)
  line L4 (-145, -43) -> (-132, -43)
  line L5 (-129.0798, -44.5715) -> (-190.7755, -44.5715)
  line L6 (-124.349, -39.5715) -> (-125.3776, -42.086)
  line L7 (-118.849, -23.5713) -> (-124.349, -39.5715)
  curve K1 (-118.849, 33.4285) -> (-118.849, -23.5713)
  line L8 (-188.849, 45.4285) -> (-130.849, 45.4285)
  curve K2 (-200.849, -23.5713) -> (-200.849, 33.4285)
  line L9 (-194.5583, -41.8718) -> (-200.849, -23.5713)
  line L10 (-143, -8) -> (-143, -17)
  line L11 (-135, -8) -> (-143, -8)
  line L12 (-135, -17) -> (-135, -8)
  line L13 (-135, -17) -> (-143, -17)
  circle C1 centre (-160, -0.9088) radius 20
  arc A1 centre (-190.7755, -40.5715) radius 4 clockwise from (-190.7755, -44.5715) to (-194.5583, -41.8718)
  arc A2 centre (-129.0798, -40.5715) radius 4 clockwise from (-125.3776, -42.086) to (-129.0798, -44.5715)
  arc A3 centre (-130.849, 33.4285) radius 12 clockwise from (-130.849, 45.4285) to (-118.849, 33.4285)
  arc A4 centre (-188.849, 33.4285) radius 12 clockwise from (-200.849, 33.4285) to (-188.849, 45.4285)
  point P22 (-143, -17)
  point P25 (-135, -17)
  coincident L2 P22
  perpendicular L2 L10
  perpendicular L10 L11
  coincident L2 P25
  perpendicular L2 L12
extrude "Extrude24" cut sketch "Sketch30" profile of L2 C1 L10 L11 L12 L13 against normal blind 15
combine "Combine1"
sketch "Sketch31" plane through (0, 0, 42.6235) normal (0, 0, -1) x axis (1, 0, 0)
  line L1 (-135, -17) -> (-135, -8)
  line L2 (-132, -17) -> (-135, -17)
  line L3 (-132, -43) -> (-132, -17)
  line L4 (-145, -43) -> (-132, -43)
  line L5 (-145, -17) -> (-145, -43)
  line L6 (-143, -17) -> (-145, -17)
  line L7 (-143, -11.4445) -> (-143, -17)
  line L8 (-135, -8) -> (-141.2993, -8)
  line L9 (-129.0798, -44.5715) -> (-190.7755, -44.5715)
  line L10 (-124.349, -39.5715) -> (-125.3776, -42.086)
  line L11 (-118.849, -23.5713) -> (-124.349, -39.5715)
  curve K1 (-118.849, 33.4285) -> (-118.849, -23.5713)
  line L12 (-188.849, 45.4285) -> (-130.849, 45.4285)
  curve K2 (-200.849, -23.5713) -> (-200.849, 33.4285)
  line L13 (-194.5583, -41.8718) -> (-200.849, -23.5713)
  line L14 (-145, -17) -> (-145, -43)
  line L15 (-145, -43) -> (-132, -43)
  line L16 (-132, -43) -> (-132, -17)
  line L17 (-132, -17) -> (-135, -17)
  line L18 (-135, -17) -> (-135, -8)
  line L19 (-135, -8) -> (-141.2993, -8)
  line L20 (-145, -17) -> (-143, -17)
  line L21 (-145, -43) -> (-145, -17)
  line L22 (-132, -43) -> (-145, -43)
  line L23 (-132, -17) -> (-132, -43)
  line L24 (-135, -17) -> (-132, -17)
  line L25 (-135, -8) -> (-135, -17)
  line L26 (-143, -8) -> (-135, -8)
  line L27 (-143, -17) -> (-143, -8)
  arc A1 centre (-160, -0.9088) radius 20 clockwise from (-143, -11.4445) to (-141.2993, -8)
  arc A2 centre (-190.7755, -40.5715) radius 4 clockwise from (-190.7755, -44.5715) to (-194.5583, -41.8718)
  arc A3 centre (-129.0798, -40.5715) radius 4 clockwise from (-125.3776, -42.086) to (-129.0798, -44.5715)
  arc A4 centre (-130.849, 33.4285) radius 12 clockwise from (-130.849, 45.4285) to (-118.849, 33.4285)
  arc A5 centre (-188.849, 33.4285) radius 12 clockwise from (-200.849, 33.4285) to (-188.849, 45.4285)
  point P19 (-118.849, -23.5713)
  dimension "d201" distance P19 L16 = 13.151
extrude "Extrude25" new body sketch "Sketch31" profile of L1 L2 L3 L4 L5 L6 L7 L8 L14 L15 L16 L17 L18 L19 L20 L21 L22 L23 L24 L25 L26 L27 against normal blind 1.2
chamfer "Chamfer13" distance 2
sketch "Sketch32" plane through (0, 0, 42.6235) normal (0, 0, -1) x axis (1, 0, 0)
  line L1 (-135, -17) -> (-135, -8)
  line L2 (-132, -17) -> (-135, -17)
  line L3 (-132, -43) -> (-132, -17)
  line L4 (-145, -43) -> (-132, -43)
  line L5 (-145, -17) -> (-145, -43)
  line L6 (-143, -17) -> (-145, -17)
  line L7 (-143, -11.4445) -> (-143, -17)
  line L8 (-135, -8) -> (-141.2993, -8)
  line L9 (-129.0798, -44.5715) -> (-190.7755, -44.5715)
  line L10 (-124.349, -39.5715) -> (-125.3776, -42.086)
  line L11 (-118.849, -23.5713) -> (-124.349, -39.5715)
  curve K1 (-118.849, 33.4285) -> (-118.849, -23.5713)
  line L12 (-188.849, 45.4285) -> (-130.849, 45.4285)
  curve K2 (-200.849, -23.5713) -> (-200.849, 33.4285)
  line L13 (-194.5583, -41.8718) -> (-200.849, -23.5713)
  line L14 (-159.849, 45.4285) -> (-159.9277, -44.5715)
  line L15 (-202.6914, -0.8339) -> (-117.0076, -0.9088)
  arc A1 centre (-160, -0.9088) radius 20 clockwise from (-143, -11.4445) to (-141.2993, -8)
  arc A2 centre (-190.7755, -40.5715) radius 4 clockwise from (-190.7755, -44.5715) to (-194.5583, -41.8718)
  arc A3 centre (-129.0798, -40.5715) radius 4 clockwise from (-125.3776, -42.086) to (-129.0798, -44.5715)
  arc A4 centre (-130.849, 33.4285) radius 12 clockwise from (-130.849, 45.4285) to (-118.849, 33.4285)
  arc A5 centre (-188.849, 33.4285) radius 12 clockwise from (-200.849, 33.4285) to (-188.849, 45.4285)
  circle C1 centre (-128.3685, 35.5017) radius 3
  circle C2 centre (-191.3468, 35.5568) radius 3
  circle C3 centre (-191.4104, -37.2444) radius 3
  circle C4 centre (-128.4322, -37.2995) radius 3
  point P27 (-159.9277, -44.5715)
  point P28 (-159.849, 45.4285)
  point P29 (-117.0076, -0.9088)
  point P30 (-202.6914, -0.8339)
  point P34 (-128.4322, -37.2995)
  midpoint L9 P27
  midpoint L12 P28
  coincident K1 P29
  coincident K2 P30
  perpendicular L14 L15
  symmetric L14 C1 C2
  symmetric L15 C2 C3
  symmetric L14 C3 C4
  dimension "d179" diameter C1 = 6
  dimension "d180" distance L11 P34 = 4.6
offset_faces "OffsetFaces2" distance -0.3
align "Align2"
combine "Combine2"
align "Align3"
sketch "Sketch33" plane through (0, 0, -3) normal (0, 0, -1) x axis (1, 0, 0)
  line L1 (-189.5, -38) -> (-194.0726, -38)
  line L2 (-185.5, -43) -> (-185.5, -42)
  line L3 (-134.5, -43) -> (-185.5, -43)
  line L4 (-134.5, -42) -> (-134.5, -43)
  line L5 (-125.9274, -38) -> (-130.5, -38)
  line L6 (-120.949, -23.5174) -> (-125.9274, -38)
  curve K1 (-120.949, -23.5174) -> (-121.0005, 32.9025)
  line L7 (-189, 43) -> (-131, 43)
  curve K2 (-198.9995, 32.9025) -> (-199.051, -23.5174)
  line L8 (-194.0726, -38) -> (-199.051, -23.5174)
  line L9 (-160, -43) -> (-160, 43)
  line L10 (-119.1454, -0.0241) -> (-200.8546, -0.0241)
  circle C1 centre (-130, 36.9675) radius 5.5
  circle C2 centre (-190, -30) radius 5.5
  arc A1 centre (-189.5, -42) radius 4 clockwise from (-189.5, -38) to (-185.5, -42)
  arc A2 centre (-130.5, -42) radius 4 clockwise from (-134.5, -42) to (-130.5, -38)
  arc A3 centre (-131, 33) radius 10 clockwise from (-131, 43) to (-121.0005, 32.9025)
  arc A4 centre (-189, 33) radius 10 clockwise from (-198.9995, 32.9025) to (-189, 43)
  circle C3 centre (-130, -30) radius 5.5
  circle C4 centre (-190, 36.9675) radius 5.5
  circle C5 centre (-190, 36.9675) radius 1.6
  circle C6 centre (-130, 36.9675) radius 1.6
  circle C7 centre (-190, -30) radius 1.6
  circle C8 centre (-130, -30) radius 1.6
  point P24 (-160, 43)
  point P25 (-160, -43)
  point P26 (-200.8546, -0.0241)
  point P27 (-119.1454, -0.0241)
  midpoint L7 P24
  midpoint L3 P25
  coincident K2 P26
  coincident K1 P27
  perpendicular L9 L10
  concentric C4 C5
  concentric C1 C6
  concentric C2 C7
  concentric C3 C8
  dimension "d184" diameter C5 = 3.2
  dimension "d185" diameter C6 = 3.2
  dimension "d186" diameter C7 = 3.2
  dimension "d187" diameter C8 = 3.2
extrude "Extrude27" cut sketch "Sketch33" profile of C5 C6 C7 C8 against normal blind 20
sketch "Sketch34" plane through (0, 0, 7.5) normal (0, 0, -1) x axis (1, 0, 0)
  line L1 (-129.0798, -44.5715) -> (-190.7755, -44.5715)
  line L2 (-124.349, -39.5715) -> (-125.3776, -42.086)
  line L3 (-118.849, -23.5713) -> (-124.349, -39.5715)
  curve K1 (-118.849, 33.4285) -> (-118.849, -23.5713)
  line L4 (-188.849, 45.4285) -> (-130.849, 45.4285)
  curve K2 (-200.849, -23.5713) -> (-200.849, 33.4285)
  line L5 (-194.5583, -41.8718) -> (-200.849, -23.5713)
  line L6 (-135, -17) -> (-135, -8)
  line L7 (-132, -17) -> (-135, -17)
  line L8 (-132, -43) -> (-132, -17)
  line L9 (-145, -43) -> (-132, -43)
  line L10 (-145, -17) -> (-145, -43)
  line L11 (-143, -17) -> (-145, -17)
  line L12 (-143, -11.4445) -> (-143, -17)
  line L13 (-135, -8) -> (-141.2993, -8)
  arc A1 centre (-190.7755, -40.5715) radius 4 clockwise from (-190.7755, -44.5715) to (-194.5583, -41.8718)
  arc A2 centre (-129.0798, -40.5715) radius 4 clockwise from (-125.3776, -42.086) to (-129.0798, -44.5715)
  arc A3 centre (-130.849, 33.4285) radius 12 clockwise from (-130.849, 45.4285) to (-118.849, 33.4285)
  arc A4 centre (-188.849, 33.4285) radius 12 clockwise from (-200.849, 33.4285) to (-188.849, 45.4285)
  arc A5 centre (-160, -0.9088) radius 20 clockwise from (-143, -11.4445) to (-141.2993, -8)
  circle C1 centre (-190, 36.9675) radius 1.6
  circle C2 centre (-130, 36.9675) radius 1.6
  circle C3 centre (-190, -30) radius 1.6
  circle C4 centre (-130, -30) radius 1.6
  circle C5 centre (-190, 36.9675) radius 2.5
  circle C6 centre (-130, 36.9675) radius 2.5
  circle C7 centre (-130, -30) radius 2.5
  circle C8 centre (-190, -30) radius 2.5
  concentric C1 C5
  concentric C2 C6
  concentric C4 C7
  concentric C3 C8
  dimension "d192" diameter C5 = 5
  dimension "d193" diameter C6 = 5
  dimension "d194" diameter C7 = 5
  dimension "d195" diameter C8 = 5
extrude "Extrude28" cut sketch "Sketch34" profile of L8 C1 C2 C3 C4 C5 C6 C7 C8 against normal blind 5
chamfer "Chamfer14" distance 0.5
extrude "Extrude29" add of existing geometry blind 1.2
sketch "Sketch35" plane through (0, 0, 21.8) normal (0, 0, -1) x axis (1, 0, 0)
  line L1 (-141.2993, -8) -> (-143, -8)
  line L2 (-143, -8) -> (-143, -11.4445)
  line L3 (-170.15, -0.6088) -> (-170.15, -0.9088)
  line L4 (-151.85, 1.3912) -> (-168.15, 1.3912)
  line L5 (-149.85, -0.9088) -> (-149.85, -0.6088)
  line L6 (-168.15, -2.9088) -> (-151.85, -2.9088)
  arc A1 centre (-160, -0.9088) radius 20 clockwise from (-143, -11.4445) to (-141.2993, -8)
  arc A2 centre (-168.15, -0.9088) radius 2 clockwise from (-168.15, -2.9088) to (-170.15, -0.9088)
  arc A3 centre (-168.15, -0.6088) radius 2 clockwise from (-170.15, -0.6088) to (-168.15, 1.3912)
  arc A4 centre (-151.85, -0.6088) radius 2 clockwise from (-151.85, 1.3912) to (-149.85, -0.6088)
  arc A5 centre (-151.85, -0.9088) radius 2 clockwise from (-149.85, -0.9088) to (-151.85, -2.9088)
  point P6 (-170.15, -0.9088)
  point P15 (-149.85, -0.9088)
  dimension "d202" distance P6 P15 = 20.3
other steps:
move "Move5"
move "Move6"
move "Move7"
move "Move8"
extrude "Extrude3" cut sketch "Sketch33" profile of C5 C6 C7 C8 against normal blind 20
create_component "CreateComponent1"
create_component "CreateComponent1"
create_component "CreateComponent2"
create_component "CreateComponent3"
create_component "CreateComponent4"
create_component "CreateComponent5"
create_component "CreateComponent1"
create_component "CreateComponent2"
create_component "CreateComponent3"
create_component "CreateComponent4"
create_component "CreateComponent6"
create_component "CreateComponent1"
create_component "CreateComponent2"
create_component "CreateComponent3"
create_component "CreateComponent7"
create_component "CreateComponent8"
create_component "CreateComponent1"
create_component "CreateComponent2"
create_component "CreateComponent3"
create_component "CreateComponent4"
create_component "CreateComponent9"
create_component "CreateComponent10"
create_component "CreateComponent1"
create_component "CreateComponent2"
create_component "CreateComponent3"
create_component "CreateComponent4"
create_component "CreateComponent11"
create_component "CreateComponent12"
create_component "CreateComponent13"
create_component "CreateComponent14"
create_component "CreateComponent15"
create_component "CreateComponent16"
create_component "CreateComponent17"
create_component "CreateComponent18"
create_component "CreateComponent2"

design "FINAL ALI"
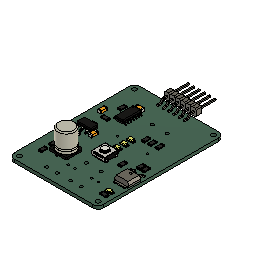
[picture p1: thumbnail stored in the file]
description: KiCad electronic assembly
part number: FINAL ALI 1
description: Part Number
part number: Ceramic
part number: Contacts
part number: Contacts (Mirror #1)
part number: Overcoat
part number: Resistor-1206
part number: SOT-223
part number: Body
part number: Contact
part number: ContactClone
base_feature "Base Feature1"
base_feature "Base Feature1"
base_feature "Base Feature1"
base_feature "Base Feature1"
base_feature "Base Feature1"
base_feature "Base Feature1"
base_feature "Base Feature1"
base_feature "Base Feature1"
base_feature "Base Feature1"
base_feature "Base Feature1"
base_feature "Base Feature1"
base_feature "Base Feature1"
base_feature "Base Feature1"
base_feature "Base Feature1"
base_feature "Base Feature1"
base_feature "Base Feature1"
base_feature "Base Feature1"
base_feature "Base Feature1"
base_feature "Base Feature1"
base_feature "Base Feature1"
base_feature "Base Feature1"
base_feature "Base Feature1"
base_feature "Base Feature1"
base_feature "Base Feature1"
base_feature "Base Feature1"
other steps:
create_component "CreateComponent1"
create_component "CreateComponent1"
create_component "CreateComponent2"
create_component "CreateComponent3"
create_component "CreateComponent4"
create_component "CreateComponent2"
create_component "CreateComponent3"
create_component "CreateComponent1"
create_component "CreateComponent2"
create_component "CreateComponent3"
create_component "CreateComponent4"
create_component "CreateComponent5"
create_component "CreateComponent1"
create_component "CreateComponent2"
create_component "CreateComponent3"
create_component "CreateComponent4"
create_component "CreateComponent6"
create_component "CreateComponent1"
create_component "CreateComponent7"
create_component "CreateComponent1"
create_component "CreateComponent2"
create_component "CreateComponent8"
create_component "CreateComponent1"
create_component "CreateComponent2"
create_component "CreateComponent1"
create_component "CreateComponent2"
create_component "CreateComponent3"
create_component "CreateComponent4"
create_component "CreateComponent3"
create_component "CreateComponent4"
create_component "CreateComponent9"
create_component "CreateComponent10"

design "PCB TEST"
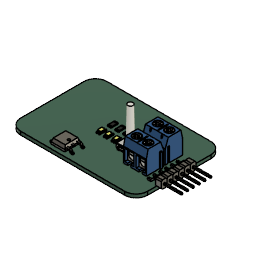
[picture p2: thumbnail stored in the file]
description: KiCad electronic assembly
part number: Final Device 1
description: Part Number
part number: Ceramic
part number: Contacts
part number: Contacts (Mirror #1)
part number: Overcoat
part number: Resistor-1206
part number: Final Device 1.3.1
part number: Final Device 1.3.2
part number: Header_SMD_01x06_P2.54mm_Horizontal_Male
part number: Final Device 1.5.1
base_feature "Base Feature1"
base_feature "Base Feature1"
base_feature "Base Feature1"
base_feature "Base Feature1"
base_feature "Base Feature1"
base_feature "Base Feature1"
base_feature "Base Feature1"
base_feature "Base Feature1"
base_feature "Base Feature1"
base_feature "Base Feature1"
base_feature "Base Feature1"
base_feature "Base Feature1"
base_feature "Base Feature1"
base_feature "Base Feature1"
base_feature "Base Feature1"
base_feature "Base Feature1"
base_feature "Base Feature1"
base_feature "Base Feature1"
base_feature "Base Feature1"
base_feature "Base Feature1"
base_feature "Base Feature1"
base_feature "Base Feature1"
base_feature "Base Feature1"
base_feature "Base Feature1"
base_feature "Base Feature1"
base_feature "Base Feature1"
base_feature "Base Feature1"
base_feature "Base Feature1"
base_feature "Base Feature1"
base_feature "Base Feature1"
base_feature "Base Feature1"
base_feature "Base Feature1"
base_feature "Base Feature1"
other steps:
create_component "CreateComponent1"
create_component "CreateComponent1"
create_component "CreateComponent2"
create_component "CreateComponent3"
create_component "CreateComponent4"
create_component "CreateComponent2"
create_component "CreateComponent1"
create_component "CreateComponent2"
create_component "CreateComponent3"
create_component "CreateComponent1"
create_component "CreateComponent4"
create_component "CreateComponent5"
create_component "CreateComponent1"
create_component "CreateComponent2"
create_component "CreateComponent3"
create_component "CreateComponent4"
create_component "CreateComponent6"
create_component "CreateComponent1"
create_component "CreateComponent2"
create_component "CreateComponent1"
create_component "CreateComponent2"
create_component "CreateComponent3"
create_component "CreateComponent4"
create_component "CreateComponent3"
create_component "CreateComponent4"
create_component "CreateComponent7"
create_component "CreateComponent1"
create_component "CreateComponent2"
create_component "CreateComponent1"
create_component "CreateComponent2"
create_component "CreateComponent3"
create_component "CreateComponent4"
create_component "CreateComponent3"
create_component "CreateComponent4"
create_component "CreateComponent8"
create_component "CreateComponent1"
create_component "CreateComponent2"
create_component "CreateComponent9"
create_component "CreateComponent1"
create_component "CreateComponent2"
create_component "CreateComponent3"
create_component "CreateComponent10"
create_component "CreateComponent11"

design "FINALALI"
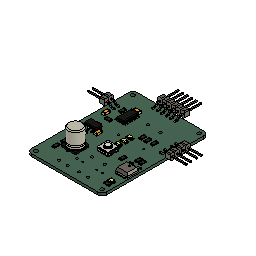
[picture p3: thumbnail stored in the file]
description: KiCad electronic assembly
part number: FINALALI 1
